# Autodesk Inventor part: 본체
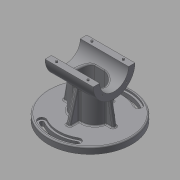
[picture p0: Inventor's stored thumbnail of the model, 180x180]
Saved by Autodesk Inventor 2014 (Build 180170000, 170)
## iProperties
Created: 2015-12
Part Number: 본체
Material: 일반
Document SubType Name: Modeling
Designer: mduedu
Density: 1 g/cm^3
Appearance: 기본값
Mass: 219.298 g
Surface Area: 580.346 cm^2
Volume: 219.298 cm^3
Author: mduedu
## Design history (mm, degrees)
sketch "스케치1"
  geometry: C1 r 65 at (0, 0); 1 further point
  constraints: 1 centre point, 1 coincident
  dimensions: "d124" = 130 diameter of C1
extrude "돌출1" new body sketch "스케치1" distance "d3" = 10; taper "d4" = 0 deg
sketch "스케치2"
  geometry: C1 r 32.5 at (80, 0); 1 further point
  constraints: 1 centre point, 1 horizontal alignment
  dimensions: "d5" = 65 diameter of C1; "d125" = 80 distance of C1.centre point (0, 0)
extrude "돌출2" join sketch "스케치2" stored distance "d7" = 75; taper "d8" = 0 deg
sketch "스케치3"
  geometry: L1 (-27.5, -20)-(27.5, -20); L2 (27.5, -20)-(27.5, 20); L3 (27.5, 20)-(-27.5, 20); L4 (-27.5, 20)-(-27.5, -20); L5 (-27.5, -20)-(27.5, 20); L6 (27.5, -20)-(-27.5, 20); 1 further point
  constraints: 12 end point, 2 midpoint, 2 parallel, 1 horizontal, 1 perpendicular
  dimensions: "d9" = 55 distance of L2.end L3.end; "d11" = 40 distance of L1.end L2.end
extrude "돌출3" new body sketch "스케치3" stored distance "d12" = 75; taper "d13" = 0 deg
fillet "모깎기1"
fillet "모깎기2"
feature "결합1"
  node "솔리드2"
sketch "스케치4"
  geometry: L1 (-37.5, 47.5)-(37.5, 47.5) reference; L2 (32.5, 47.5)-(39.112, 10); L3 (37.5, 47.5)-(37.5, 112.5) reference; L4 (65, 10)-(-65, 10) reference; 1 further point
  constraints: 2 end point, 2 point on line
  dimensions: "d15" = 5 distance from line of L2.start L3; "d126" = 80 deg angle of L2 L1
sketch "스케치5"
  geometry: L1 (10, 35)-(56.569, 22.522); L2 (10, -65)-(10, 65) reference; L3 (10, 20)-(54.383, 20) reference; A1 r 32.5 centre (80, 0) between (56.569, 22.522) and (54.383, 20) reference; 1 further point
  constraints: 2 end point, 1 point on circle, 1 point on line
  dimensions: "d127" = 75 deg angle of L1 L2; "d128" = 15 distance of L1.start L3.start
feature "리브1" dims "d19" = 1, "d20" = 6, "d21" = 0, "d22" = 0, "d23" = 1, "d24" = 1
feature "리브2" dims "d25" = 1, "d26" = 6, "d27" = 0, "d28" = 0, "d29" = 1, "d30" = 1
fillet "모깎기4" dims "d31" = 2
fillet "모깎기5" dims "d32" = 2
fillet "모깎기6" dims "d33" = 2
fillet "모깎기7" dims "d41" = 2
hole "구멍2" diameter "d44" = 45; stored, may be unused: countersink angle "d48" = 90 deg, drill point angle "d50" = 118 deg; dims "d42" = 10, "d43" = 10, "d45" = 6, "d46" = 4, "d47" = 2, "d49" = 8
sketch "스케치7" dims "d52" = 26.5
  geometry: L1 (0, 0)-(32.5, 0); L2 (0, 0)-(22.981, 22.981); A1 r 32.5 centre (0, 0) between (32.5, 0) and (22.981, 22.981) reference; 3 further points
  constraints: 4 end point, 2 point on circle, 1 coincident, 1 horizontal, 1 point on line, 3 other
  dimensions: "d51" = 45 deg angle of L2 L1
hole "구멍3" sketch "스케치7" at (18.738, 18.738) diameter "d54" = 2.459; stored, may be unused: countersink angle "d58" = 90 deg, drill point angle "d60" = 118 deg; dims "d55" = 8, "d56" = 4, "d57" = 2, "d59" = 10
sketch "스케치9"
  geometry: L1 (-75, 82.5)-(75, 82.5); L2 (75, 82.5)-(75, 0); L3 (75, 0)-(-75, 0); L4 (-75, 0)-(-75, 82.5); C1 r 32.5 at (0, 0) reference; 2 further points
  constraints: 8 end point, 2 parallel, 1 coincident, 1 horizontal, 1 midpoint, 1 perpendicular
  dimensions: "d71" = 50 distance edge to line of C1 L1; "d116" = 150 distance between parallel lines of L2 L4
extrude "돌출5" cut sketch "스케치9" stored distance "d73" = 0; taper "d74" = 0 deg
node "작업 평면1"
sketch "스케치10"
  geometry: L1 (-7.5, 15)-(7.5, 15); L2 (-7.5, -15)-(7.5, -15); A1 r 20 centre (-7.5, 0) between (-7.5, 20) and (-26.977, 4.545) reference; A2 r 20 centre (7.5, 0) between (26.977, 4.545) and (7.5, 20) reference; A3 r 15 centre (-7.5, 0) between (-7.5, 15) and (-7.5, -15); A4 r 15 centre (7.5, 0) between (7.5, -15) and (7.5, 15); 1 further point
  constraints: 7 point on circle, 4 end point, 4 tangent, 3 point on line, 2 centre point, 2 coincident, 1 horizontal
  dimensions: "d77" = 5 radial gap between concentric circles of A3 A1
extrude "돌출6" cut sketch "스케치10" stored distance "d78" = 50; taper "d79" = 0 deg
fillet "모깎기10" dims "d80" = 3
sketch "스케치11"
  geometry: 2 further points
  constraints: 1 coincident
hole "구멍4" sketch "스케치11" at (0, 0) diameter "d81" = 12; stored, may be unused: countersink angle "d85" = 90 deg, drill point angle "d87" = 118 deg; dims "d82" = 8, "d83" = 40, "d84" = 10, "d86" = 10
sketch "스케치12"
  geometry: C1 r 10 at (0, 0); 1 further point
  constraints: 1 centre point, 1 coincident
  dimensions: "d88" = 20 diameter of C1
extrude "돌출7" cut sketch "스케치12" distance "d89" = 5; taper "d90" = 0 deg
chamfer "모따기1" distance "d91" = 1; stored, may be unused: second distance "d92" = 2, angle "d93" = 45 deg
fillet "모깎기11" dims "d94" = 0.5
fillet "모깎기12" dims "d115" = 0.3
sketch "스케치15"
  geometry: L1 (-75, 55)-(-75, 65) reference; L2 (0, 65)-(0, 55) reference; L3 (-75, 60)-(0, 60); C1 r 1.5 at (-62, 60); 1 further point
  constraints: 2 end point, 2 midpoint, 1 centre point, 1 point on line
  dimensions: "d117" = 3 diameter of C1; "d118" = 13 distance from line of C1.centre L1
extrude "돌출8" join sketch "스케치15" distance "d119" = 1.8; taper "d120" = 0 deg
chamfer "모따기2" distance "d121" = 0.5; stored, may be unused: second distance "d122" = 2, angle "d123" = 45 deg
sketch "스케치16"
  geometry: L1 (0, 0)-(61, 0); L2 (0, 0)-(30.5, 52.828); L3 (0, 0)-(-30.5, 52.828); L4 (0, 0)-(-61, 0); A1 r 55 centre (0, 0) between (-27.5, 47.631) and (27.5, 47.631); A2 r 61 centre (0, 0) between (-30.5, 52.828) and (30.5, 52.828); A3 r 49 centre (0, 0) between (-24.5, 42.435) and (24.5, 42.435); A4 r 6 centre (-27.5, 47.631) between (-30.5, 52.828) and (-24.5, 42.435); A5 r 6 centre (27.5, 47.631) between (30.5, 52.828) and (24.5, 42.435); A6 r 49 centre (0, 0) between (24.5, 42.435) and (-24.5, 42.435); A7 r 61 centre (0, 0) between (30.5, 52.828) and (-30.5, 52.828); 1 further point
  constraints: 15 point on circle, 8 end point, 7 centre point, 2 point on line, 1 coincident, 1 horizontal, 10 other
  dimensions: "d129" = 110 diameter of A1; "d130" = 6 radial gap between concentric circles of A1 A2; "d131" = 6 radial gap between concentric circles of A3 A1; "d134" = 180 deg dimension on point (0, 0) L1.end L4.end
extrude "돌출9" cut sketch "스케치16" distance "d136" = 3; taper "d137" = 0 deg
sketch "스케치17"
  geometry: A1 r 6 centre (27.5, 47.631) between (24.5, 42.435) and (30.5, 52.828) reference; A2 r 61 centre (0, 0) between (30.5, 52.828) and (-30.5, 52.828) reference; A3 r 6 centre (-27.5, 47.631) between (-30.5, 52.828) and (-24.5, 42.435) reference; A4 r 49 centre (0, 0) between (24.5, 42.435) and (-24.5, 42.435) reference; A5 r 58 centre (0, 0) between (29, 50.229) and (-29, 50.229); A6 r 3 centre (27.5, 47.631) between (26, 45.033) and (29, 50.229); A7 r 52 centre (0, 0) between (26, 45.033) and (-26, 45.033); A8 r 3 centre (-27.5, 47.631) between (-29, 50.229) and (-26, 45.033); 1 further point
  constraints: 8 point on circle, 4 centre point, 3 other
  dimensions: "d138" = 3 radial gap between concentric circles of A5 A2
extrude "돌출10" cut sketch "스케치17" stored distance "d139" = 3; taper "d140" = 0 deg
node "솔리드1"
mirror "대칭1"
mirror "대칭2"
pattern_circular "원형 패턴1" dims angle "d62" = 360 deg
mirror "대칭3"
mirror "대칭5"
mirror "대칭6"
mirror "대칭7"
node "투영된 루프1"
